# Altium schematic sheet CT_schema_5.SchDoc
size 291 x 159 mm
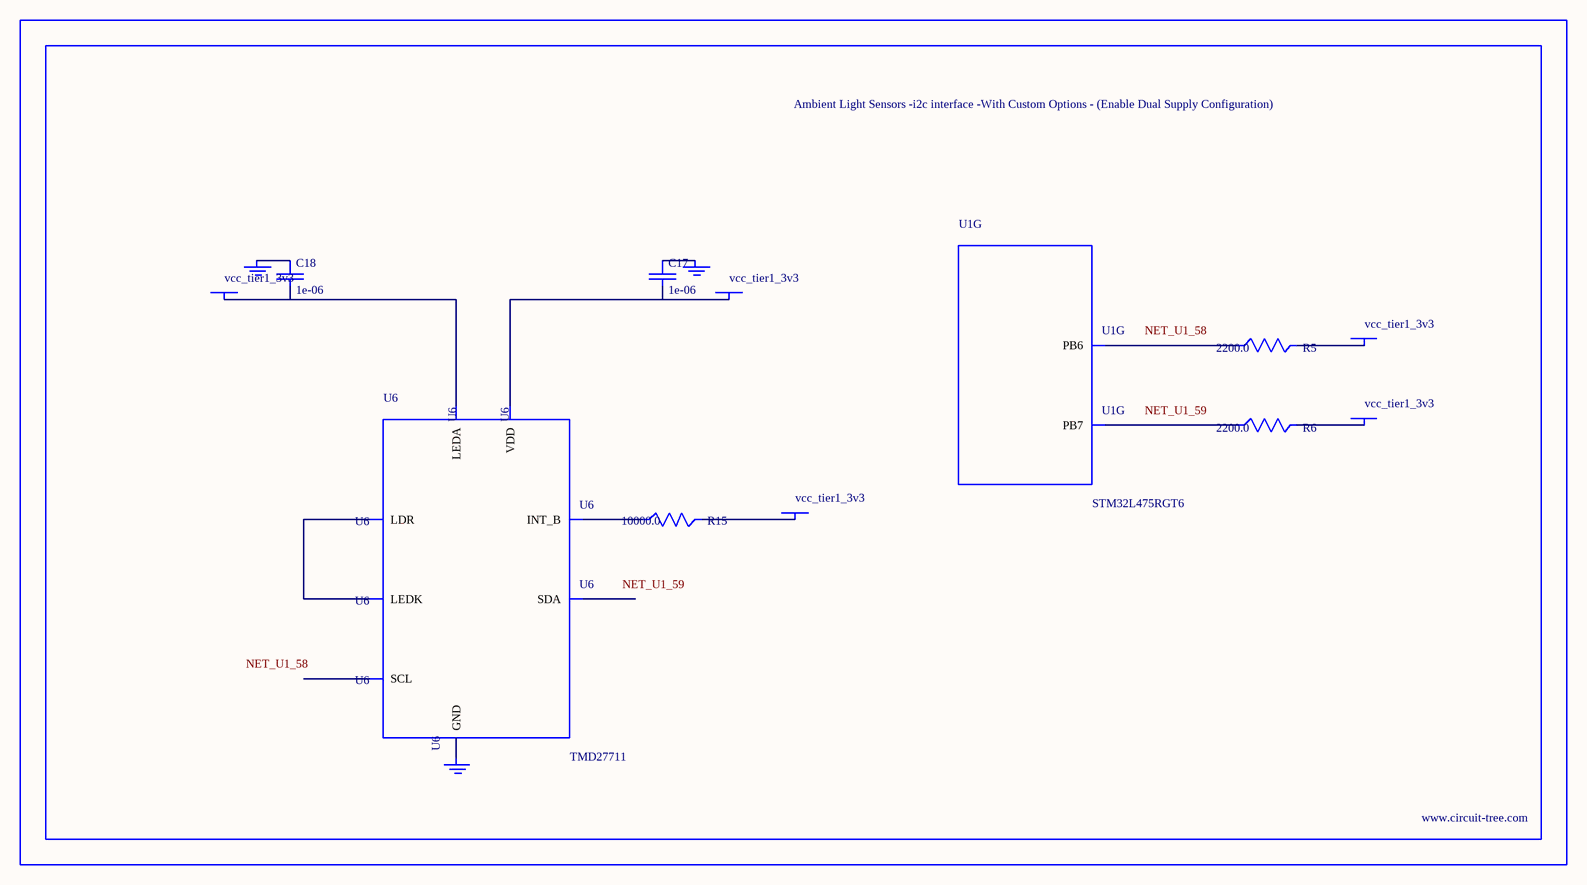
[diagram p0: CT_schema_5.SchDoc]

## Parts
BORDER4  (no value)
C17  1e-06  [C0603]
C18  1e-06  [C0603]
GND_INSTANCE_4_0  (no value)
GND_INSTANCE_4_1  (no value)
GND_INSTANCE_4_2  (no value)
POWER_INSTANCE_4_0  vcc_tier1_3v3
POWER_INSTANCE_4_1  vcc_tier1_3v3
POWER_INSTANCE_4_2  vcc_tier1_3v3
POWER_INSTANCE_4_3  vcc_tier1_3v3
POWER_INSTANCE_4_4  vcc_tier1_3v3
R5  2200.0  [R0603]
R6  2200.0  [R0603]
R15  10000.0  [R0603]
U1  STM32L475RGT6  [LQFP64]  (part G of 8)
U6  TMD27711  [SMD-8]

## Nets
NetC17_1: C17.1 GND_INSTANCE_4_0.0(GND)
NetC17_2: C17.2 POWER_INSTANCE_4_0.0(PWR) U6.1(VDD)
NetC18_1: C18.1 GND_INSTANCE_4_1.0(GND)
NetC18_2: C18.2 POWER_INSTANCE_4_1.0(PWR) U6.4(LEDA)
NetGND_INSTANCE_4_2_0: GND_INSTANCE_4_2.0(GND) U6.3(GND)
NetPOWER_INSTANCE_4_2_0: POWER_INSTANCE_4_2.0(PWR) R15.2
NetPOWER_INSTANCE_4_3_0: POWER_INSTANCE_4_3.0(PWR) R5.2
NetPOWER_INSTANCE_4_4_0: POWER_INSTANCE_4_4.0(PWR) R6.2
NetR5_1: R5.1 U1.58(PB6)
NetR6_1: R6.1 U1.59(PB7)
NetR15_1: R15.1 U6.7(INT_B)
NetU6_5: U6.5(LEDK) U6.6(LDR)

Not connected (* = marked no-connect by the designer): U6 2(SCL) 8(SDA)

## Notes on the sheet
- Labels drawn without touching a wire or pin: NET_U1_58, NET_U1_59

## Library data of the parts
BORDER4 = BORDER_PAGE4
C17 C18 = C0603C105K3RACTU
GND_INSTANCE_4_0-GND_INSTANCE_4_2 = GND
POWER_INSTANCE_4_0-POWER_INSTANCE_4_4 = PWR
R5 R6 = RC0603JR-072K2L
R15 = RC0603JR-0710KL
